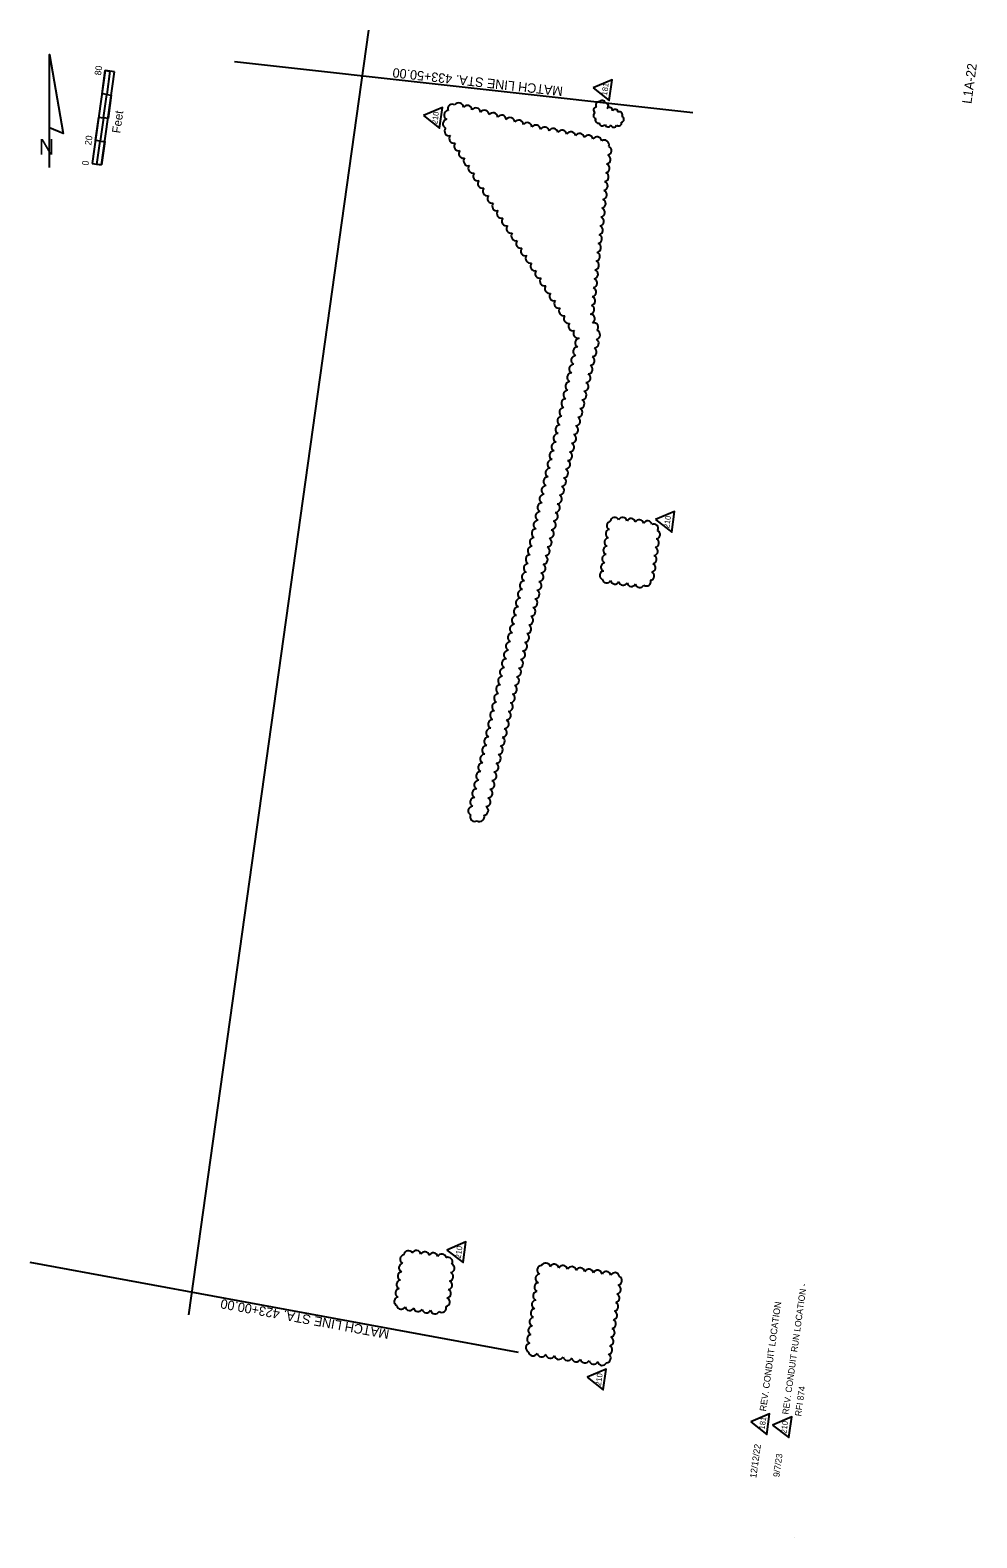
# Model space of a CAD drawing. Extents: x 930328 to 931132, y 618295 to 619577.
import ezdxf

# ---------------------------------------------------------------- set-up
doc = ezdxf.new("R2010")
doc.units = 0
for name, color, linetype in [('ActivePointCell_dp', 7, 'Continuous'), ('AdhocPoint_dp', 7, 'Continuous'), ('Cloud_dp', 7, 'Continuous'), ('MatchLines_dp', 7, 'Continuous'), ('NorthArw_dp', 7, 'Continuous'), ('Scale_dp', 7, 'Continuous'), ('TextMinor', 7, 'Continuous'), ('TextShtNo', 7, 'Continuous')]:
    doc.layers.add(name, color=color, linetype=linetype)

msp = doc.modelspace()

# ---------------------------------------------------------------- linework, layer by layer
at = {"layer": 'ActivePointCell_dp'}
msp.add_line((930462.9, 618484.8), (930615.7, 619577), dxfattribs=at)
at = {"layer": 'AdhocPoint_dp'}
msp.add_line((930977.7, 618295.3), (930977.7, 618295.3), dxfattribs=at)
at = {"layer": 'Cloud_dp'}
for points in [[(930806.3, 619527.9), (930820, 619517.2), (930822.5, 619534.7)], [(930662.3, 619504.4), (930676, 619493.7), (930678.5, 619511.2)], [(930859.3, 619160.9), (930873.1, 619150.2), (930875.5, 619167.7)], [(930682.2, 618540), (930695.9, 618529.4), (930698.3, 618546.9)], [(930801.3, 618431.9), (930815, 618421.2), (930817.5, 618438.7)], [(930940.2, 618393.9), (930953.9, 618383.3), (930956.3, 618400.8)], [(930958.8, 618391.2), (930972.5, 618380.6), (930975, 618398.1)]]:
    msp.add_lwpolyline(points, close=True, dxfattribs=at)
for centre, radius, start, end in [((930686.8, 619510.1), 3.96, 56.0314, 201.0314), ((930692.3, 619511.2), 3.96, 1.4093, 146.4093), ((930811.1, 619513.4), 2.59, 76.6227, 221.6227), ((930814, 619514.7), 2.59, 7.3419, 152.3419), ((930816.7, 619512.5), 2.59, 308.1795, 93.1795), ((930682.7, 619497.3), 3.96, 99.7513, 244.7513), ((930683.7, 619504.8), 3.96, 99.7513, 244.7513), ((930699.5, 619509.1), 3.96, 1.4093, 146.4093), ((930706.8, 619507), 3.96, 1.4093, 146.4093), ((930714.1, 619504.9), 3.96, 1.4093, 146.4093), ((930721.3, 619502.8), 3.96, 1.4093, 146.4093), ((930728.6, 619500.8), 3.96, 1.4093, 146.4093), ((930735.8, 619498.7), 3.96, 1.4093, 146.4093), ((930809.1, 619504.5), 2.59, 114.733, 259.733), ((930809.3, 619509.1), 2.59, 94.2302, 239.2302), ((930810.8, 619500.5), 2.59, 145.1509, 290.1509), ((930820.2, 619508.7), 2.59, 352.7587, 137.7587), ((930825.1, 619507.1), 2.59, 6.5554, 151.5554), ((930828.7, 619505), 2.59, 327.632, 112.632), ((930829.9, 619501.2), 2.59, 283.9994, 68.9994), ((930684.1, 619491.2), 3.96, 139.9311, 284.9311), ((930743.1, 619496.6), 3.96, 1.4093, 146.4093), ((930750.4, 619494.5), 3.96, 1.4093, 146.4093), ((930757.7, 619492.4), 3.96, 2.5284, 147.5284), ((930765.1, 619490.7), 3.96, 6.8711, 151.8711), ((930772.5, 619489.4), 3.96, 6.8711, 151.8711), ((930780, 619488), 3.96, 6.8711, 151.8711), ((930787.4, 619486.6), 3.96, 6.8711, 151.8711), ((930794.8, 619485.2), 3.96, 6.8711, 151.8711), ((930814.2, 619498.2), 2.59, 183.3784, 328.3784), ((930819, 619497.4), 2.59, 192.3062, 337.3062), ((930823.9, 619497), 2.59, 194.2695, 339.2695), ((930828, 619498.1), 2.59, 229.0551, 14.0551), ((930688.1, 619484.8), 3.96, 139.9311, 284.9311), ((930692.2, 619478.4), 3.96, 139.9311, 284.9311), ((930802.3, 619483.8), 3.96, 6.8711, 151.8711), ((930809.7, 619482.4), 3.96, 6.8711, 151.8711), ((930815.9, 619479.6), 3.96, 340.1548, 125.1548), ((930818, 619474.6), 3.96, 281.3046, 66.3046), ((930696.2, 619472), 3.96, 139.9311, 284.9311), ((930700.3, 619465.7), 3.96, 139.9311, 284.9311), ((930816.4, 619459.6), 3.96, 281.3046, 66.3046), ((930817.2, 619467.1), 3.96, 281.3046, 66.3046), ((930704.3, 619459.3), 3.96, 139.9311, 284.9311), ((930708.4, 619452.9), 3.96, 139.9311, 284.9311), ((930815.6, 619452.1), 3.96, 281.3046, 66.3046), ((930712.4, 619446.5), 3.96, 139.9311, 284.9311), ((930716.5, 619440.2), 3.96, 139.9311, 284.9311), ((930814, 619437.1), 3.96, 281.3046, 66.3046), ((930814.8, 619444.6), 3.96, 281.3046, 66.3046), ((930720.5, 619433.8), 3.96, 139.9311, 284.9311), ((930724.6, 619427.4), 3.96, 139.9311, 284.9311), ((930812.3, 619422.1), 3.96, 281.3046, 66.3046), ((930813.1, 619429.6), 3.96, 281.3046, 66.3046), ((930728.6, 619421), 3.96, 139.9311, 284.9311), ((930732.7, 619414.6), 3.96, 139.9311, 284.9311), ((930811.5, 619414.5), 3.96, 281.3046, 66.3046), ((930736.7, 619408.3), 3.96, 139.9311, 284.9311), ((930740.8, 619401.9), 3.96, 139.9311, 284.9311), ((930809.9, 619399.5), 3.96, 281.3046, 66.3046), ((930810.7, 619407), 3.96, 281.3046, 66.3046), ((930744.9, 619395.5), 3.96, 139.9311, 284.9311), ((930748.9, 619389.1), 3.96, 139.9311, 284.9311), ((930808.2, 619384.5), 3.96, 281.3046, 66.3046), ((930809.1, 619392), 3.96, 281.3046, 66.3046), ((930753, 619382.8), 3.96, 139.9311, 284.9311), ((930757, 619376.4), 3.96, 139.9311, 284.9311), ((930806.6, 619369.5), 3.96, 281.3046, 66.3046), ((930807.4, 619377), 3.96, 281.3046, 66.3046), ((930761.1, 619370), 3.96, 139.9311, 284.9311), ((930765.1, 619363.6), 3.96, 139.9311, 284.9311), ((930805.8, 619362), 3.96, 281.3046, 66.3046), ((930769.2, 619357.2), 3.96, 139.9311, 284.9311), ((930773.2, 619350.9), 3.96, 139.9311, 284.9311), ((930804.2, 619346.9), 3.96, 281.3046, 66.3046), ((930805, 619354.4), 3.96, 281.3046, 66.3046), ((930777.3, 619344.5), 3.96, 139.9311, 284.9311), ((930781.3, 619338.1), 3.96, 139.9311, 284.9311), ((930803.4, 619339.4), 3.96, 281.3046, 66.3046), ((930803.9, 619331.6), 3.96, 301.2239, 86.2239), ((930785.4, 619331.7), 3.96, 139.9311, 284.9311), ((930789.4, 619325.4), 3.96, 139.9311, 284.9311), ((930793.5, 619319), 3.96, 139.9311, 284.9311), ((930806.8, 619324.3), 3.96, 317.8491, 102.8491), ((930808.3, 619318), 3.96, 283.3225, 68.3225), ((930795, 619311.2), 3.96, 96.6253, 241.6253), ((930807.2, 619310.7), 3.96, 274.2223, 59.2223), ((930791.7, 619296.4), 3.96, 94.6359, 239.6359), ((930793.4, 619303.8), 3.96, 94.6359, 239.6359), ((930803.7, 619296), 3.96, 274.2223, 59.2223), ((930805.4, 619303.4), 3.96, 274.2223, 59.2223), ((930788.3, 619281.7), 3.96, 94.6359, 239.6359), ((930790, 619289), 3.96, 94.6359, 239.6359), ((930800.2, 619281.3), 3.96, 274.2223, 59.2223), ((930802, 619288.7), 3.96, 274.2223, 59.2223), ((930785, 619266.9), 3.96, 94.6359, 239.6359), ((930786.7, 619274.3), 3.96, 94.6359, 239.6359), ((930798.5, 619274), 3.96, 274.2223, 59.2223), ((930783.3, 619259.6), 3.96, 94.6359, 239.6359), ((930795, 619259.3), 3.96, 274.2223, 59.2223), ((930796.7, 619266.6), 3.96, 274.2223, 59.2223), ((930779.9, 619244.8), 3.96, 94.6359, 239.6359), ((930781.6, 619252.2), 3.96, 94.6359, 239.6359), ((930791.5, 619244.5), 3.96, 274.2223, 59.2223), ((930793.3, 619251.9), 3.96, 274.2223, 59.2223), ((930776.6, 619230.1), 3.96, 94.6359, 239.6359), ((930778.3, 619237.5), 3.96, 94.6359, 239.6359), ((930788.1, 619229.8), 3.96, 274.2223, 59.2223), ((930789.8, 619237.2), 3.96, 274.2223, 59.2223), ((930773.2, 619215.4), 3.96, 94.6359, 239.6359), ((930774.9, 619222.7), 3.96, 94.6359, 239.6359), ((930786.3, 619222.5), 3.96, 274.2223, 59.2223), ((930771.5, 619208), 3.96, 94.6359, 239.6359), ((930782.9, 619207.8), 3.96, 274.2223, 59.2223), ((930784.6, 619215.1), 3.96, 274.2223, 59.2223), ((930768.2, 619193.3), 3.96, 94.6359, 239.6359), ((930769.8, 619200.6), 3.96, 94.6359, 239.6359), ((930779.4, 619193.1), 3.96, 274.2223, 59.2223), ((930781.1, 619200.4), 3.96, 274.2223, 59.2223), ((930764.8, 619178.5), 3.96, 94.6359, 239.6359), ((930766.5, 619185.9), 3.96, 94.6359, 239.6359), ((930775.9, 619178.4), 3.96, 274.2223, 59.2223), ((930777.7, 619185.7), 3.96, 274.2223, 59.2223), ((930761.4, 619163.8), 3.96, 94.6359, 239.6359), ((930763.1, 619171.2), 3.96, 94.6359, 239.6359), ((930774.2, 619171), 3.96, 274.2223, 59.2223), ((930759.7, 619156.4), 3.96, 94.6359, 239.6359), ((930770.7, 619156.3), 3.96, 274.2223, 59.2223), ((930772.4, 619163.6), 3.96, 274.2223, 59.2223), ((930821.7, 619155.8), 3.73, 99.5383, 244.5383), ((930824.7, 619159), 3.73, 27.1915, 172.1915), ((930831.4, 619159.1), 3.73, 9.5383, 154.5383), ((930838.5, 619158.1), 3.73, 9.5383, 154.5383), ((930845.5, 619157.1), 3.73, 9.5383, 154.5383), ((930852.6, 619156.1), 3.73, 9.5383, 154.5383), ((930857.9, 619153.4), 3.73, 330.9317, 115.9317), ((930756.4, 619141.7), 3.96, 94.6359, 239.6359), ((930758.1, 619149.1), 3.96, 94.6359, 239.6359), ((930767.2, 619141.6), 3.96, 274.2223, 59.2223), ((930769, 619148.9), 3.96, 274.2223, 59.2223), ((930819.7, 619141.7), 3.73, 99.5383, 244.5383), ((930820.7, 619148.8), 3.73, 99.5383, 244.5383), ((930858.6, 619141.2), 3.73, 279.5383, 64.5383), ((930859.5, 619148.2), 3.73, 279.5383, 64.5383), ((930753, 619127), 3.96, 94.6359, 239.6359), ((930754.7, 619134.3), 3.96, 94.6359, 239.6359), ((930763.8, 619126.9), 3.96, 274.2223, 59.2223), ((930765.5, 619134.2), 3.96, 274.2223, 59.2223), ((930817.7, 619127.6), 3.73, 99.5383, 244.5383), ((930818.7, 619134.7), 3.73, 99.5383, 244.5383), ((930856.6, 619127.1), 3.73, 279.5383, 64.5383), ((930857.6, 619134.1), 3.73, 279.5383, 64.5383), ((930751.3, 619119.6), 3.96, 94.6359, 239.6359), ((930762, 619119.5), 3.96, 274.2223, 59.2223), ((930815.7, 619113.5), 3.73, 99.5383, 244.5383), ((930816.7, 619120.6), 3.73, 99.5383, 244.5383), ((930855.6, 619120), 3.73, 279.5383, 64.5383), ((930748, 619104.9), 3.96, 94.6359, 239.6359), ((930749.7, 619112.2), 3.96, 94.6359, 239.6359), ((930758.6, 619104.8), 3.96, 274.2223, 59.2223), ((930760.3, 619112.2), 3.96, 274.2223, 59.2223), ((930817.8, 619110.8), 3.73, 189.5383, 334.5383), ((930824.9, 619109.8), 3.73, 189.5383, 334.5383), ((930831.9, 619108.8), 3.73, 189.5383, 334.5383), ((930839, 619107.8), 3.73, 189.5383, 334.5383), ((930846, 619106.8), 3.73, 189.5383, 334.5383), ((930851.7, 619108.2), 3.73, 232.3336, 17.3336), ((930854.6, 619113), 3.73, 279.5383, 64.5383), ((930744.6, 619090.1), 3.96, 94.6359, 239.6359), ((930746.3, 619097.5), 3.96, 94.6359, 239.6359), ((930755.1, 619090.1), 3.96, 274.2223, 59.2223), ((930756.8, 619097.4), 3.96, 274.2223, 59.2223), ((930741.2, 619075.4), 3.96, 94.6359, 239.6359), ((930742.9, 619082.8), 3.96, 94.6359, 239.6359), ((930751.6, 619075.4), 3.96, 274.2223, 59.2223), ((930753.4, 619082.7), 3.96, 274.2223, 59.2223), ((930739.6, 619068), 3.96, 94.6359, 239.6359), ((930749.9, 619068), 3.96, 274.2223, 59.2223), ((930736.2, 619053.3), 3.96, 94.6359, 239.6359), ((930737.9, 619060.7), 3.96, 94.6359, 239.6359), ((930746.4, 619053.3), 3.96, 274.2223, 59.2223), ((930748.2, 619060.7), 3.96, 274.2223, 59.2223), ((930732.8, 619038.6), 3.96, 94.6359, 239.6359), ((930734.5, 619045.9), 3.96, 94.6359, 239.6359), ((930742.9, 619038.6), 3.96, 274.2223, 59.2223), ((930744.7, 619046), 3.96, 274.2223, 59.2223), ((930729.5, 619023.8), 3.96, 94.6359, 239.6359), ((930731.1, 619031.2), 3.96, 94.6359, 239.6359), ((930739.5, 619023.9), 3.96, 274.2223, 59.2223), ((930741.2, 619031.3), 3.96, 274.2223, 59.2223), ((930727.8, 619016.5), 3.96, 94.6359, 239.6359), ((930737.7, 619016.5), 3.96, 274.2223, 59.2223), ((930724.4, 619001.7), 3.96, 94.6359, 239.6359), ((930726.1, 619009.1), 3.96, 94.6359, 239.6359), ((930734.3, 619001.8), 3.96, 274.2223, 59.2223), ((930736, 619009.2), 3.96, 274.2223, 59.2223), ((930721.1, 618987), 3.96, 94.6359, 239.6359), ((930722.7, 618994.4), 3.96, 94.6359, 239.6359), ((930730.8, 618987.1), 3.96, 274.2223, 59.2223), ((930732.5, 618994.5), 3.96, 274.2223, 59.2223), ((930717.7, 618972.3), 3.96, 94.6359, 239.6359), ((930719.4, 618979.6), 3.96, 94.6359, 239.6359), ((930727.3, 618972.4), 3.96, 274.2223, 59.2223), ((930729.1, 618979.8), 3.96, 274.2223, 59.2223), ((930716, 618964.9), 3.96, 94.6359, 239.6359), ((930725.6, 618965.1), 3.96, 274.2223, 59.2223), ((930712.6, 618950.2), 3.96, 94.6359, 239.6359), ((930714.3, 618957.5), 3.96, 94.6359, 239.6359), ((930722.1, 618950.4), 3.96, 274.2223, 59.2223), ((930723.9, 618957.7), 3.96, 274.2223, 59.2223), ((930709.3, 618935.4), 3.96, 94.6359, 239.6359), ((930711, 618942.8), 3.96, 94.6359, 239.6359), ((930718.6, 618935.6), 3.96, 274.2223, 59.2223), ((930720.4, 618943), 3.96, 274.2223, 59.2223), ((930705.9, 618920.7), 3.96, 94.6359, 239.6359), ((930707.6, 618928.1), 3.96, 94.6359, 239.6359), ((930715.2, 618920.9), 3.96, 274.2223, 59.2223), ((930716.9, 618928.3), 3.96, 274.2223, 59.2223), ((930704.2, 618913.3), 3.97, 94.6359, 239.6359), ((930713.4, 618913.6), 3.96, 274.2223, 59.2223), ((930705.8, 618908.3), 3.96, 155.7405, 300.7405), ((930710, 618908.2), 3.96, 236.5029, 21.5029), ((930645.2, 618525), 3.81, 99.5383, 244.5383), ((930646.2, 618532.2), 3.81, 99.5383, 244.5383), ((930649.4, 618535.6), 3.81, 29.4069, 174.4069), ((930656.2, 618535.8), 3.81, 9.5383, 154.5383), ((930663.4, 618534.8), 3.81, 9.5383, 154.5383), ((930670.6, 618533.8), 3.81, 9.5383, 154.5383), ((930677.8, 618532.8), 3.81, 9.5383, 154.5383), ((930683.1, 618530), 3.81, 329.995, 114.995), ((930684.8, 618524.6), 3.81, 279.5383, 64.5383), ((930766, 618525.1), 3.89, 9.5383, 154.5383), ((930773.3, 618524.1), 3.89, 9.5383, 154.5383), ((930780.7, 618523), 3.89, 9.5383, 154.5383), ((930643.2, 618510.6), 3.81, 99.5383, 244.5383), ((930644.2, 618517.8), 3.81, 99.5383, 244.5383), ((930683.8, 618517.4), 3.81, 279.5383, 64.5383), ((930761.3, 618515.7), 3.89, 99.5383, 244.5383), ((930762.7, 618522.9), 3.89, 93.443, 238.443), ((930788.1, 618522), 3.89, 9.5383, 154.5383), ((930795.4, 618521), 3.89, 9.5383, 154.5383), ((930802.8, 618519.9), 3.89, 9.5383, 154.5383), ((930810.1, 618518.9), 3.89, 9.5383, 154.5383), ((930817.5, 618517.9), 3.89, 9.5383, 154.5383), ((930824.8, 618516.9), 3.89, 9.5383, 154.5383), ((930827, 618514), 3.89, 279.5383, 64.5383), ((930642.2, 618503.4), 3.81, 99.5383, 244.5383), ((930681.8, 618503), 3.81, 279.5383, 64.5383), ((930682.8, 618510.2), 3.81, 279.5383, 64.5383), ((930759.2, 618501), 3.89, 99.5383, 244.5383), ((930760.3, 618508.4), 3.89, 99.5383, 244.5383), ((930824.9, 618499.3), 3.89, 279.5383, 64.5383), ((930826, 618506.6), 3.89, 279.5383, 64.5383), ((930641.2, 618496.2), 3.81, 99.5383, 244.5383), ((930643.3, 618493.4), 3.81, 189.5383, 334.5383), ((930650.5, 618492.4), 3.81, 189.5383, 334.5383), ((930657.7, 618491.4), 3.81, 189.5383, 334.5383), ((930664.9, 618490.4), 3.81, 189.5383, 334.5383), ((930672.1, 618489.4), 3.81, 189.5383, 334.5383), ((930677.8, 618490.8), 3.81, 234.2333, 19.2333), ((930680.8, 618495.8), 3.81, 279.5383, 64.5383), ((930757.2, 618486.3), 3.89, 99.5383, 244.5383), ((930758.2, 618493.6), 3.89, 99.5383, 244.5383), ((930823.9, 618491.9), 3.89, 279.5383, 64.5383), ((930756.2, 618478.9), 3.89, 99.5383, 244.5383), ((930821.9, 618477.2), 3.89, 279.5383, 64.5383), ((930822.9, 618484.6), 3.89, 279.5383, 64.5383), ((930754.1, 618464.2), 3.89, 99.5383, 244.5383), ((930755.1, 618471.6), 3.89, 99.5383, 244.5383), ((930819.8, 618462.5), 3.89, 279.5383, 64.5383), ((930820.8, 618469.8), 3.89, 279.5383, 64.5383), ((930753.1, 618456.9), 3.89, 99.5383, 244.5383), ((930755.2, 618454), 3.89, 189.5383, 334.5383), ((930762.6, 618453), 3.89, 189.5383, 334.5383), ((930770, 618451.9), 3.89, 189.5383, 334.5383), ((930777.3, 618450.9), 3.89, 189.5383, 334.5383), ((930817.4, 618448), 3.89, 273.443, 58.443), ((930818.8, 618455.1), 3.89, 279.5383, 64.5383), ((930784.7, 618449.9), 3.89, 189.5383, 334.5383), ((930792, 618448.8), 3.89, 189.5383, 334.5383), ((930799.4, 618447.8), 3.89, 189.5383, 334.5383), ((930806.7, 618446.8), 3.89, 189.5383, 334.5383), ((930814.1, 618445.8), 3.89, 189.5383, 334.5383)]:
    msp.add_arc(centre, radius, start, end, dxfattribs=at)
at = {"layer": 'MatchLines_dp'}
for p, q in [((930891.1, 619506.7), (930501.8, 619550.1)), ((930742.9, 618452.9), (930328.2, 618529.4))]:
    msp.add_line(p, q, dxfattribs=at)
at = {"layer": 'NorthArw_dp'}
msp.add_line((930344.7, 619460.3), (930344.7, 619556.3), dxfattribs=at)
msp.add_lwpolyline([(930344.7, 619493.9), (930344.7, 619556.3), (930356.3, 619489.1)], close=True, dxfattribs=at)
at = {"layer": 'Scale_dp'}
for p, q in [((930392, 619542.7), (930380.9, 619463.5)), ((930388.9, 619462.4), (930399.9, 619541.6)), ((930399.9, 619541.6), (930392, 619542.7)), ((930380.9, 619463.5), (930388.9, 619462.4))]:
    msp.add_line(p, q, dxfattribs=at)
for points in [[(930393.2, 619522.3), (930389.2, 619522.9), (930392, 619542.7), (930395.9, 619542.2)], [(930394.4, 619502), (930390.4, 619502.5), (930393.2, 619522.3), (930397.1, 619521.8)], [(930387.6, 619482.7), (930383.7, 619483.3), (930386.4, 619503.1), (930390.4, 619502.5)], [(930388.9, 619462.4), (930384.9, 619462.9), (930387.6, 619482.7), (930391.6, 619482.2)]]:
    msp.add_lwpolyline(points, close=True, dxfattribs=at)

# ---------------------------------------------------------------- texts
at = {"layer": 'Cloud_dp'}
for s, p in [('181', (930818.1, 619521.2)), ('210', (930674, 619496.8)), ('210', (930871, 619153.3)), ('210', (930693.9, 618532.5)), ('210', (930813, 618424.3)), ('181', (930952, 618387.2)), ('210', (930970.5, 618383.7))]:
    msp.add_text(s, height=4.8, rotation=82.0383, dxfattribs=at).set_placement(p)
at = {"layer": 'MatchLines_dp'}
for s, rotation, p in [('MATCH LINE STA. 433+50.00', 173.6425, (930781, 619528.8)), ('MATCH LINE STA. 423+00.00', 169.5563, (930633.7, 618472.1))]:
    msp.add_text(s, height=8, rotation=rotation, dxfattribs=at).set_placement(p)
at = {"layer": 'NorthArw_dp'}
msp.add_text('N', height=13.4, dxfattribs=at).set_placement((930335.6, 619471.1))
at = {"layer": 'Scale_dp'}
for s, height, p in [('80', 5.6, (930388.3, 619538.2)), ('Feet', 7.2, (930404.7, 619489)), ('20', 5.6, (930380, 619478.8)), ('0', 5.6, (930377.6, 619461.6))]:
    msp.add_text(s, height=height, rotation=82.0794, dxfattribs=at).set_placement(p)
at = {"layer": 'TextMinor'}
for s, height, p in [('REV. CONDUIT RUN LOCATION - ', 5.376, (930972.3, 618399.9)), ('REV. CONDUIT LOCATION', 5.6, (930953.2, 618402.6)), ('RFI 874', 5.38, (930983, 618398.4)), ('12/12/22', 5.6, (930944.9, 618345.8)), ('9/7/23', 5.38, (930964.5, 618346.7))]:
    msp.add_text(s, height=height, rotation=82.0383, dxfattribs=at).set_placement(p)
at = {"layer": 'TextShtNo'}
msp.add_text('L1A-22', height=8, rotation=82.0383, dxfattribs=at).set_placement((931127.6, 619514))

doc.saveas('drawing.dxf')
